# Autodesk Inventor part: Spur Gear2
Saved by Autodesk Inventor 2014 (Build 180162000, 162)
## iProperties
Created: 2010-12
Part Number: Spur Gear2
Material: Steel
Document SubType Name: Modeling
Designer: Thom Tremblay
Categories: <?xml version="1.0" encoding="UTF-16"?> <MemberInstance><Categories><FamilyTemplate><FamilyTemplateParameter ValueType="xs:double" Id="1" ObjectReferenceKey="da
Density: 1 g/cm^3
Appearance: Steel
CustomPartVersion: 1
Author: Thom Tremblay
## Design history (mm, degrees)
sketch "Sketch1"
  geometry: C1 r 42.825 at (0, 0)
  constraints: 1 centre point
  dimensions: "d0" = 85.64993 diameter of C1 (= da_da)
extrude "Extrusion1" new body sketch "Sketch1" distance "d1" = 12 (= da_b); taper "d2" = 0 deg
workplane "Work Plane2"
sketch "Sketch2"
  geometry: C1 r 42.825 at (0, 0) reference; C2 r 41.837 at (0, 0)
  constraints: 1 centre point, 1 coincident
  dimensions: "d3" = 83.67347 diameter of C2 (= da_dw)
feature "Pitch Diameter" sketch "Sketch2" dims "d4" = 10, "d5" = 0
workplane "Work Plane8"
workplane "Work Plane9"
feature "Spur Gear" dims "da_b" = 12, "da_d" = 82, "da_aw" = 50, "da_da" = 85.64993, "da_df" = 81.29409, "da_dw" = 83.67347, angle "da_beta" = 0 deg, "da_lefttooth" = 0, "da_righttooth" = 0
node "Keyway1"
body "Solid1"
body "Srf1"
feature "Hub Keyway"
other parameters: "d17" = 0, "d34" = 0.38312 (computed from da_z), "d39" = 0, "d41" = 0, "d47" = 0, "d48" = 0
